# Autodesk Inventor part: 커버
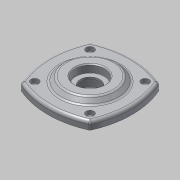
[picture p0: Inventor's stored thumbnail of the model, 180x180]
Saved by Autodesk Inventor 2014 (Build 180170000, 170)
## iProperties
Created: 2016-05
Part Number: 커버
Document SubType Name: Modeling
Designer: mduedu
Density: 2.71 g/cm^3
Material: 알루미늄 6061
Appearance: Aluminum - Flat
Author: mduedu
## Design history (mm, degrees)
sketch "스케치1"
  geometry: L1 (0, 0)-(-35.355, 35.355); L2 (0, 0)-(0, 43); L3 (0, 0)-(43, 0); C1 r 25 at (0, 0); A1 r 85.579 centre (0, -42.579) between (35.355, 35.355) and (-35.355, 35.355); A2 r 85.579 centre (42.579, 0) between (-35.355, 35.355) and (-35.355, -35.355); A3 r 85.579 centre (0, 42.579) between (-35.355, -35.355) and (35.355, -35.355); A4 r 85.579 centre (-42.579, 0) between (35.355, -35.355) and (35.355, 35.355); 1 further point
  constraints: 10 point on circle, 6 end point, 5 centre point, 2 horizontal alignment, 2 vertical alignment, 1 coincident, 1 equal radius, 2 other
  dimensions: "d28" = 86 dimension on A4 A2; "d30" = 50 diameter of C1; "d31" = 45 deg angle of L2 L1; "d32" = 100 distance of A3.end L1.end
extrude "돌출1" new body sketch "스케치1" distance "d0" = 8; taper "d1" = 0 deg
extrude "돌출2" join sketch "스케치1" distance "d2" = 12; taper "d3" = 0 deg
sketch "스케치2"
  geometry: C1 r 30 at (0, 0); 1 further point
  constraints: 1 centre point, 1 coincident
  dimensions: "d4" = 60 diameter of C1
extrude "돌출3" join sketch "스케치2" distance "d5" = 5; taper "d6" = -45 deg
sketch "스케치3"
  geometry: C1 r 1.621 at (-28.284, 28.284) reference; C2 r 1.621 at (28.284, 28.284) reference; C3 r 1.621 at (28.284, -28.284) reference; C4 r 1.621 at (-28.284, -28.284) reference; 1 further point
hole "구멍1" sketch "스케치3" at (28.284, 28.284), (-28.284, 28.284), (-28.284, -28.284), (28.284, -28.284) diameter "d7" = 4.5; stored, may be unused: countersink angle "d11" = 90 deg, drill point angle "d13" = 118 deg; dims "d8" = 6, "d9" = 8, "d10" = 4.4, "d12" = 8
fillet "모깎기1" dims "d14" = 3
sketch "스케치4"
  geometry: L1 (-23.757, 13)-(23.757, 13) reference; L2 (25, -12)-(-25, -12) reference; L3 (0, -12)-(0, 13); L4 (-20, -12)-(-20, 0); L5 (-20, 0)-(-15, 0); L6 (-15, 0)-(-15, 3); L7 (-15, 3)-(-10, 3); L8 (-10, 3)-(-10, 5); L9 (-10, 5)-(-15, 5); L10 (-15, 5)-(-15, 13); 1 further point
  constraints: 16 end point, 6 parallel, 2 midpoint, 2 point on line, 1 perpendicular
  dimensions: "d15" = 40 diameter of L4 L3; "d16" = 30 diameter of L10 L3; "d17" = 8 distance of L9.end L10.end; "d18" = 12 distance of L4.start L4.end; "d19" = 3 distance of L5.end L6.end; "d20" = 30 diameter of L6 L3; "d21" = 20 diameter of L8 L3
revolve "회전1" sketch "스케치4" stored, may be unused: angle "d22" = 90 deg
fillet "모깎기2" dims "d23" = 3
fillet "모깎기3" dims "d24" = 0.3
chamfer "모따기1" distance "d25" = 1; stored, may be unused: second distance "d26" = 2, angle "d27" = 45 deg
node "솔리드1"
node "참조2"
node "참조3"
node "참조4"
node "참조5"
